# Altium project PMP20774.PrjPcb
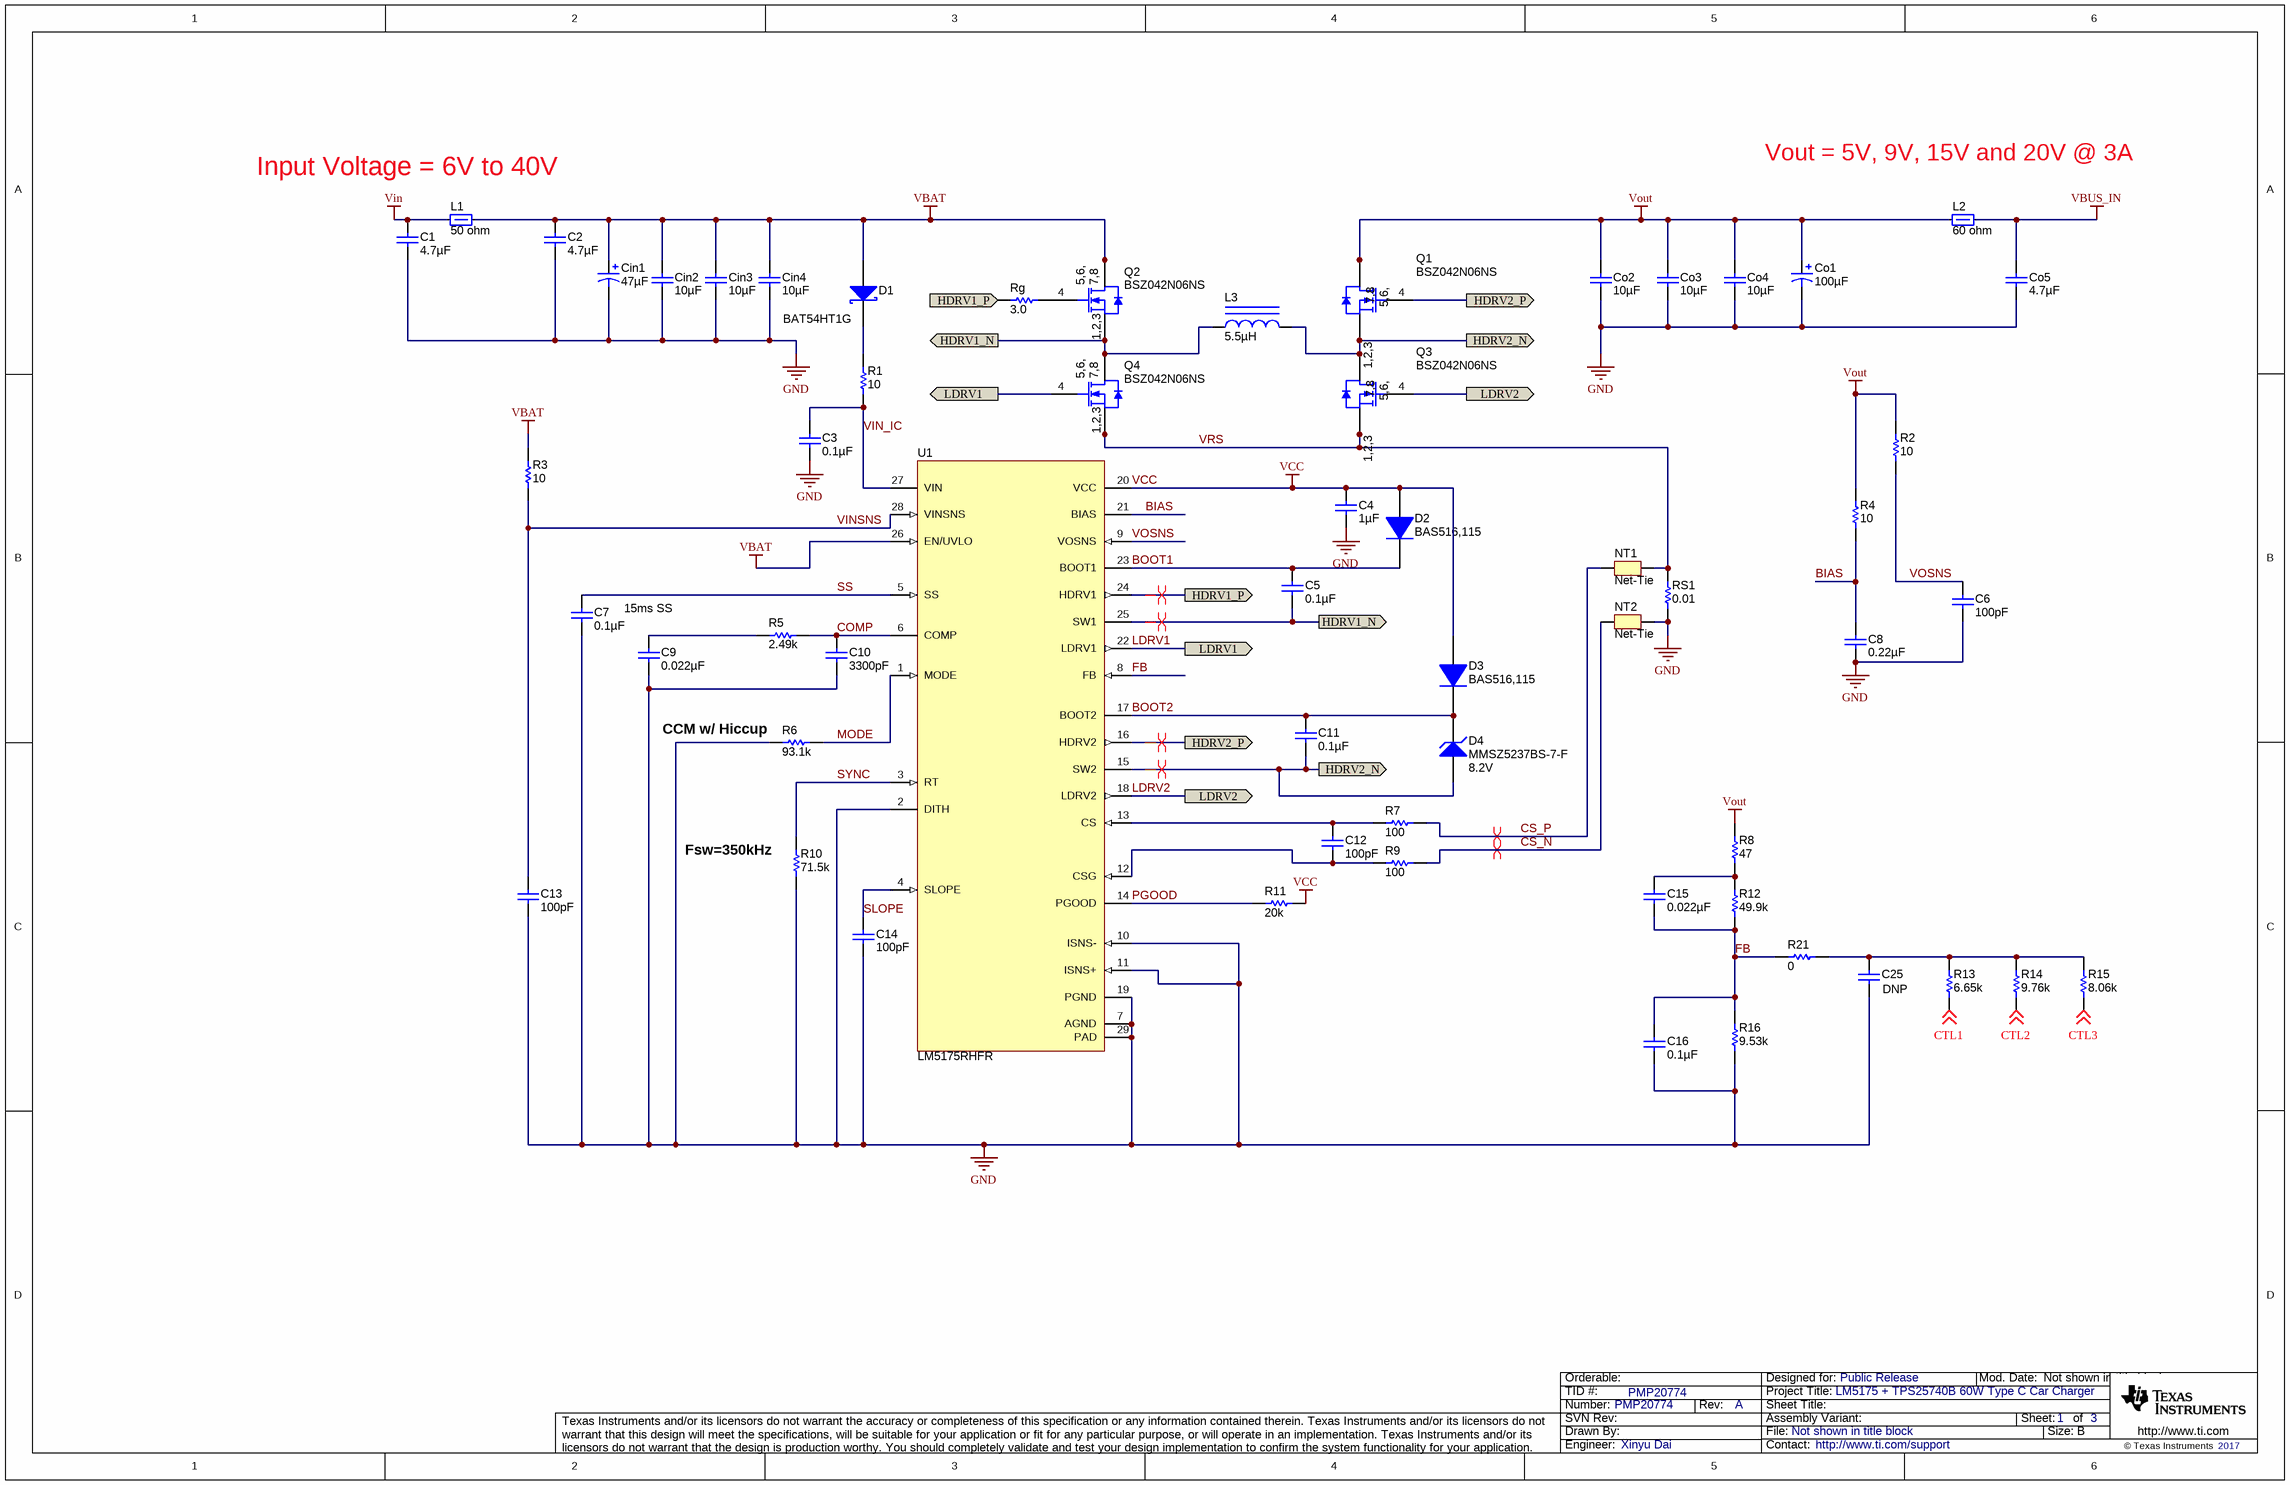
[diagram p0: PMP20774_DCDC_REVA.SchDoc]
CopyrightYear: 2017; PCB_Layout: Xinyu Dai; PCB_Rev: A; PRJ_Customer: Public Release; PRJ_Engineer: Xinyu Dai; PRJ_Number: PMP20774; PRJ_Title: LM5175 + TPS25740B 60W Type C Car Charger; SCH_Rev: A; TechSupport: http://www.ti.com/support; TID: PMP20774
3 sheets, 81 parts. Net scope: flat (ports and power ports of the same name join across sheets).
Board file: PMP20774_REVA.PcbDoc
Sheets:
  PMP20774_DCDC_REVA.SchDoc
  PMP20774_PD_REVA.SchDoc
  PMP20774_REVA_Hardware.SchDoc

## Sheet PMP20774_DCDC_REVA.SchDoc
size 431 x 279 mm; Date: Not shown in title block; ApprovedBy: Not shown in title block; CheckedBy: Not shown in title block; Author: Not shown in title block; CompanyName: Not shown in title block; Engineer: Not shown in title block; Organization: Not shown in title block; Address1: Not shown in title block; Address2: Not shown in title block; Address3: Not shown in title block; Address4: Not shown in title block; DocumentNumber: 1; Revision: Use project parameter SCH_Rev; SheetNumber: 1; SheetTotal: 3; PageSetup: Record=PageOptions¦CenterHorizontal=True¦CenterVertical=True¦PrintScale=1.00¦XCorrection=1.00¦YCorrection=1.00¦PrintKind=0¦BorderSize=5000000¦LeftOffset=0¦BottomOffset=0¦Orientation=2¦PaperLength=1000¦PaperWidth=1000¦Scale=100¦PaperSource=15¦PrintQuality=600¦MediaType=1¦DitherType=10¦PaperKind=Letter¦PrintScaleMode=1

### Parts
(Parts that share a designator on the sheet are numbered #1, #2 ... from top to bottom, then left to right.)
C1  ValueDisplayed: 4.7µF  [1206_180]  (hidden comment: GRM31CR71H475KA12L)
C2  ValueDisplayed: 4.7µF  [1206_180]  (hidden comment: GRM31CR71H475KA12L)
C3  ValueDisplayed: 0.1µF  [0402L]  (hidden comment: GRM155R71H104ME14D)
C4  ValueDisplayed: 1µF  [0402]  (hidden comment: GRM155R70J105KA12D)
C5  ValueDisplayed: 0.1µF  [0402L]  (hidden comment: GRM155R71H104ME14D)
C6  ValueDisplayed: 100pF  [0402L]  (hidden comment: CC0402KRX7R9BB101)
C7  ValueDisplayed: 0.1µF  [0402L]  (hidden comment: GRM155R71H104ME14D)
C8  ValueDisplayed: 0.22µF  [0402L]  (hidden comment: C1005X5R1E224M050BC)
C9  ValueDisplayed: 0.022µF  [0402L]  (hidden comment: GCM155R71H223KA55D)
C10  ValueDisplayed: 3300pF  [0402]  (hidden comment: GRM155R72A332KA01D)
C11  ValueDisplayed: 0.1µF  [0402L]  (hidden comment: GRM155R71H104ME14D)
C12  ValueDisplayed: 100pF  [0402L]  (hidden comment: CC0402KRX7R9BB101)
C13  ValueDisplayed: 100pF  [0402L]  (hidden comment: CC0402KRX7R9BB101)
C14  ValueDisplayed: 100pF  [0402L]  (hidden comment: CC0402KRX7R9BB101)
C15  ValueDisplayed: 0.022µF  [0402L]  (hidden comment: GCM155R71H223KA55D)
C16  ValueDisplayed: 0.1µF  [0402L]  (hidden comment: GRM155R71H104ME14D)
C25  DNP  [0402L]
Cin1  ValueDisplayed: 47µF  [WCAP-ASLI_630x770]  (hidden comment: 865080645012)
Cin2  ValueDisplayed: 10µF  [1210_270]  (hidden comment: GRM32ER71H106MA12)
Cin3  ValueDisplayed: 10µF  [1210_270]  (hidden comment: GRM32ER71H106MA12)
Cin4  ValueDisplayed: 10µF  [1210_270]  (hidden comment: GRM32ER71H106MA12)
Co1  ValueDisplayed: 100µF  [WCAP-ASLI_630x770]  (hidden comment: 865080445010)
Co2  ValueDisplayed: 10µF  [1210_270]  (hidden comment: GRM32ER71H106MA12)
Co3  ValueDisplayed: 10µF  [1210_270]  (hidden comment: GRM32ER71H106MA12)
Co4  ValueDisplayed: 10µF  [1210_270]  (hidden comment: GRM32ER71H106MA12)
Co5  ValueDisplayed: 4.7µF  [1206_180]  (hidden comment: GRM31CR71H475KA12L)
D1  BAT54HT1G  [SOD-323]
D2  BAS516,115  [SOD-523]
D3  BAS516,115  [SOD-523]
D4  MMSZ5237BS-7-F  value 8.2V  [sod-323]
L1  value 50 ohm  [1206L]  (hidden comment: BLM31SN500SN1L)
L2  value 60 ohm  [1206L]  (hidden comment: FBMJ3216HM600-T)
L3  ValueDisplayed: 5.5µH  [WE-HC6]  (hidden comment: 744325550)
NT1  Net-Tie  [Net-Tie_10mil]  (net tie, no BOM)
NT2  Net-Tie  [Net-Tie_10mil]  (net tie, no BOM)
Q1  BSZ042N06NS  [PG-TSDSON-8]
Q2  BSZ042N06NS  [PG-TSDSON-8]
Q3  BSZ042N06NS  [PG-TSDSON-8]
Q4  BSZ042N06NS  [PG-TSDSON-8]
R1  ValueDisplayed: 10  [0402L]  (hidden comment: CRCW040210R0JNED)
R2  ValueDisplayed: 10  [0402L]  (hidden comment: CRCW040210R0JNED)
R3  ValueDisplayed: 10  [0402L]  (hidden comment: CRCW040210R0JNED)
R4  ValueDisplayed: 10  [0402L]  (hidden comment: CRCW040210R0JNED)
R5  ValueDisplayed: 2.49k  [0402L]  (hidden comment: CRCW04022K49FKED)
R6  ValueDisplayed: 93.1k  [0402L]  (hidden comment: CRCW040293K1FKED)
R7  ValueDisplayed: 100  [0402L]  (hidden comment: CRCW0402100RFKED)
R8  ValueDisplayed: 47  [0402L]  (hidden comment: CRCW040247R0JNED)
R9  ValueDisplayed: 100  [0402L]  (hidden comment: CRCW0402100RFKED)
R10  ValueDisplayed: 71.5k  [0402L]  (hidden comment: CRCW040271K5FKED)
R11  ValueDisplayed: 20k  [0402L]  (hidden comment: CRCW040220K0JNED)
R12  ValueDisplayed: 49.9k  [0402L]  (hidden comment: CRCW040249K9FKED)
R13  ValueDisplayed: 6.65k  [0402L]  (hidden comment: CRCW04026K65FKED)
R14  ValueDisplayed: 9.76k  [0402L]  (hidden comment: CRCW04029K76FKED)
R15  ValueDisplayed: 8.06k  [0402L]  (hidden comment: CRCW04028K06FKED)
R16  ValueDisplayed: 9.53k  [0402L]  (hidden comment: CRCW04029K53FKED)
R21#1  ValueDisplayed: 0  [0402L]  (hidden comment: CRCW04020000Z0ED)
Rg  ValueDisplayed: 3.0  [0402L]  (hidden comment: CRCW04023R00JNED)
RS1  ValueDisplayed: 0.01  [0612]  (hidden comment: PRL1632-R010-F-T1)
U1  LM5175RHFR  [RHF0028A]

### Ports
HDRV1_N, HDRV1_P (out), HDRV2_N, HDRV2_P (out), LDRV1 (out), LDRV2 (out)

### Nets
GND: C1.2 C2.2 C3.2 C4.2 C6.2 C7.2 C8.2 C9.2 C10.2 C13.1 C14.2 C16.2 C25.2 Cin1.2(-) Cin2.2 Cin3.2 Cin4.2 Co1.2(-) Co2.2 Co3.2 Co4.2 Co5.2 NT2.1 R6.2 R10.1 R16.1 RS1.1 U1.2(DITH) U1.7(AGND) U1.10(ISNS-) U1.11(ISNS+) U1.19(PGND) U1.29(PAD)
VBAT: C2.1 Cin1.1(+) Cin2.1 Cin3.1 Cin4.1 D1.2(A) L1.2 Q2.5(D) Q2.6(D) Q2.7(D) Q2.8(D) Q2.9(D) R3.1 U1.26(EN/UVLO)
VBUS_IN: Co5.1 L2.2
VCC: C4.1 D2.2(A) D3.2(A) R11.2 U1.20(VCC)
Vin: C1.1 L1.1
Vout: Co1.1(+) Co2.1 Co3.1 Co4.1 L2.1 Q1.5(D) Q1.6(D) Q1.7(D) Q1.8(D) Q1.9(D) R2.2 R4.2 R8.1
BIAS: C8.1 R4.1 U1.21(BIAS)
BOOT1: C5.1 D2.1(K) U1.23(BOOT1)
BOOT2: C11.2 D3.1(K) D4.1(K) U1.17(BOOT2)
COMP: C10.1 R5.2 U1.6(COMP)
CS_N: NT2.2 R9.2
CS_P: NT1.2 R7.2
CTL1: R13.1 ; off-sheet CTL1
CTL2: R14.1 ; off-sheet CTL2
CTL3: R15.1 ; off-sheet CTL3
FB: C15.2 C16.1 R12.1 R16.2 R21#1.1 U1.8(FB)
HDRV1_N: C5.2 L3.1 Q2.1(S) Q2.2(S) Q2.3(S) Q4.5(D) Q4.6(D) Q4.7(D) Q4.8(D) Q4.9(D) U1.25(SW1) ; port HDRV1_N
HDRV1_P: Rg.1 U1.24(HDRV1) ; port HDRV1_P
HDRV2_N: C11.1 D4.2(A) L3.2 Q1.1(S) Q1.2(S) Q1.3(S) Q3.5(D) Q3.6(D) Q3.7(D) Q3.8(D) Q3.9(D) U1.15(SW2) ; port HDRV2_N
HDRV2_P: Q1.4(G) U1.16(HDRV2) ; port HDRV2_P
LDRV1: Q4.4(G) U1.22(LDRV1) ; port LDRV1
LDRV2: Q3.4(G) U1.18(LDRV2) ; port LDRV2
MODE: R6.1 U1.1(MODE)
PGOOD: R11.1 U1.14(PGOOD)
SLOPE: C14.1 U1.4(SLOPE)
SS: C7.1 U1.5(SS)
SYNC: R10.2 U1.3(RT)
VIN_IC: C3.1 R1.1 U1.27(VIN)
VINSNS: C13.2 R3.2 U1.28(VINSNS)
VOSNS: C6.1 R2.1 U1.9(VOSNS)
VRS: NT1.1 Q3.1(S) Q3.2(S) Q3.3(S) Q4.1(S) Q4.2(S) Q4.3(S) RS1.2
NetC9_1: C9.1 R5.1
NetC12_1: C12.1 R7.1 U1.13(CS)
NetC12_2: C12.2 R9.1 U1.12(CSG)
NetC15_1: C15.1 R8.2 R12.2
NetC25_1: C25.1 R13.2 R14.2 R15.2 R21#1.2
NetD1_1: D1.1(K) R1.2
NetQ2_4: Q2.4(G) Rg.2

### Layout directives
differential pair: CS_N, CS_P, HDRV1_N, HDRV1_P, HDRV2_N, HDRV2_P

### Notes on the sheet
- Input Voltage = 6V to 40V
- Vout = 5V, 9V, 15V and 20V @ 3A
- 15ms SS
- (near R6) CCM w/ Hiccup
- (near R10) Fsw=350kHz

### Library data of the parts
C1 C2 = GRM31CR71H475KA12L: CAP, CERM, 4.7 µF, 50 V, +/- 10%, X7R, 1206; Manufacturer: MuRata; Polarized: N; CompType: Capacitor; Value: 4.7uF; U/M: EA; Cap_F: 0.0000047; Tolerance_%: 10; Value1: Unknown; VDC_V: 50; Value2: 50V; TaMin_C: -55; TaMax_C: 125; Cap_Case: 2220; SizeArea_mm2: 5.12; SizeAreaWB_mm2: 10.92; SizeX_mm: 3.2; SizeY_mm: 1.6; SizeZ_mm: 1.8; AEC Category: Q200
C3 C5 C11 = GRM155R71H104ME14D: CAP, CERM, 0.1 µF, 50 V, +/- 20%, X7R, 0402; Manufacturer: MuRata; Polarized: N; CompType: Capacitor; Value: 0.1uF; U/M: EA; Cap_F: 0.0000001; Tolerance_%: 20; Value1: Unknown; VDC_V: 50; Value2: 50V; TaMin_C: -55; TaMax_C: 125; Cap_Case: 0402; AEC Category: Q200; SizeArea_mm2: 0.5; SizeAreaWB_mm2: 3; SizeX_mm: 1; SizeZ_mm: 0.6
C4 = GRM155R70J105KA12D: CAP, CERM, 1 µF, 6.3 V, +/- 10%, X7R, 0402; Manufacturer: MuRata; Polarized: N; CompType: Capacitor; Value: 1uF; U/M: EA; Cap_F: 0.000001; Tolerance_%: 10; Value1: Unknown; VDC_V: 6.3; Value2: 6.3V; TaMin_C: -55; TaMax_C: 125; AEC Category: Q200; SizeArea_mm2: 0.5; SizeAreaWB_mm2: 3; SizeX_mm: 1; SizeZ_mm: 0.6
C6 C13 = CC0402KRX7R9BB101: CAP, CERM, 100 pF, 50 V, +/- 10%, X7R, 0402; Manufacturer: Yageo America; Polarized: N; CompType: Capacitor; Value: 100pF; U/M: EA; Cap_F: 0.0000000001; Tolerance_%: 10; Value1: Unknown; VDC_V: 50; Value2: 50V; TaMin_C: -55; TaMax_C: 125; Cap_Case: 0402; AEC Category: Q200
C7 C16 = GRM155R71H104ME14D: CAP, CERM, 0.1 µF, 50 V, +/- 20%, X7R, 0402; Manufacturer: MuRata; Polarized: N; CompType: Capacitor; Value: 0.1uF; U/M: EA; Cap_F: 0.0000001; Tolerance_%: 20; Value1: Unknown; VDC_V: 50; Value2: 50V; TaMin_C: -55; TaMax_C: 125; Cap_Case: 0402; SizeArea_mm2: 0.5; SizeAreaWB_mm2: 3; SizeX_mm: 1; SizeZ_mm: 0.6; AEC Category: Q200
C8 = C1005X5R1E224M050BC: CAP, CERM, 0.22 µF, 25 V, +/- 20%, X5R, 0402; Manufacturer: TDK; Polarized: N; CompType: Capacitor; Value: 0.22uF; U/M: EA; Cap_F: 0.00000022; Tolerance_%: 20; Value1: Unknown; VDC_V: 25; Value2: 25V; TaMin_C: -55; TaMax_C: 85; Cap_Case: 0402; AEC Category: Q200
C9 C15 = GCM155R71H223KA55D: CAP, CERM, 0.022 µF, 50 V, +/- 10%, C0G/NP0, 0402; Manufacturer: MuRata; Polarized: N; CompType: Capacitor; Value: 0.022uF; U/M: EA; Cap_F: 0.000000022; Tolerance_%: 10; Value1: Unknown; VDC_V: 50; Value2: 50V; TaMin_C: -55; TaMax_C: 125; Cap_Case: 0402; AEC Category: Q200; SizeArea_mm2: 0.5; SizeAreaWB_mm2: 3; SizeX_mm: 1; SizeZ_mm: 0.6
C10 = GRM155R72A332KA01D: CAP, CERM, 3300 pF, 100 V, +/- 10%, X7R, 0402; Manufacturer: MuRata; Polarized: N; CompType: Capacitor; Value: 3300pF; U/M: EA; Cap_F: 0.0000000033; Tolerance_%: 10; Value1: Unknown; VDC_V: 100; Value2: 100V; TaMin_C: -55; TaMax_C: 125; AEC Category: Q200; SizeArea_mm2: 0.5; SizeAreaWB_mm2: 3; SizeX_mm: 1; SizeZ_mm: 0.6
C12 C14 = CC0402KRX7R9BB101: CAP, CERM, 100 pF, 50 V, +/- 10%, X7R, 0402; Manufacturer: Yageo America; Polarized: N; CompType: Capacitor; Value: 100pF; U/M: EA; Cap_F: 0.0000000001; Tolerance_%: 10; Value1: Unknown; VDC_V: 50; Value2: 50V; TaMin_C: -55; TaMax_C: 125; Cap_Case: 0402; AEC Category: Q200; SizeArea_mm2: 0.5; SizeAreaWB_mm2: 3; SizeX_mm: 1; SizeZ_mm: 0.6
C25 = GRM155R70J105MA12D: CAP, CERM, 1 µF, 6.3 V, +/- 20%, X7R, 0402; Manufacturer: MuRata; Polarized: N; CompType: Capacitor; Value: 1uF; ValueDisplayed: 1µF; U/M: EA; Cap_F: 0.000001; Tolerance_%: 20; Value1: Unknown; VDC_V: 6.3; Value2: 6.3V; TaMin_C: -55; TaMax_C: 125; Cap_Case: 0402; SizeArea_mm2: 0.5; SizeAreaWB_mm2: 3; SizeX_mm: 1; SizeZ_mm: 0.6; AEC Category: Q200
Cin1 = 865080645012: CAP, AL, 47 µF, 50 V, +/- 20%, SMD; Manufacturer: Wurth Elektronik; Polarized: Y; CompType: Capacitor; Value: 47uF; U/M: EA; Cap_F: 0.000047; Tolerance_%: 20; Value1: Unknown; VDC_V: 50; Value2: 50V; IRMS_A: 0.23; TaMin_C: -55; TaMax_C: 105; Cap_Case: 6.3x7.7mm; SizeAreaWB_mm2: 79.98; SizeArea_mm2: 48.18; SizeX_mm: 7.3; SizeY_mm: 6.6; SizeZ_mm: 7.7; AEC Category: Q200; AEC Qualified: N
Cin2-Cin4 Co2-Co4 = GRM32ER71H106MA12: CAP, CERM, 10 µF, 50 V, +/- 20%, X7R, 1210; Manufacturer: MuRata; Polarized: N; CompType: Capacitor; Value: 10uF; U/M: EA; Cap_F: 0.00001; Tolerance_%: 20; Value1: Unknown; VDC_V: 50; Value2: 50V; TaMin_C: -55; TaMax_C: 125; Cap_Case: 1210; AEC Category: Q200; SizeArea_mm2: 8; SizeAreaWB_mm2: 14.7; SizeX_mm: 3.2; SizeY_mm: 2.5; SizeZ_mm: 2.7
Co1 = 865080445010: CAP, AL, 100 µF, 25 V, +/- 20%, SMD; Manufacturer: Wurth Elektronik; Polarized: Y; CompType: Capacitor; Value: 100uF; U/M: EA; Cap_F: 0.0001; Tolerance_%: 20; Value1: Unknown; VDC_V: 25; Value2: 25V; IRMS_A: 0.29; TaMin_C: -55; TaMax_C: 105; Cap_Case: 6.3x7.7mm; SizeAreaWB_mm2: 79.98; SizeArea_mm2: 48.18; SizeX_mm: 7.3; SizeY_mm: 6.6; SizeZ_mm: 7.7; AEC Category: Q200; AEC Qualified: N
Co5 = GRM31CR71H475KA12L: CAP, CERM, 4.7 µF, 50 V, +/- 10%, X7R, 1206; Manufacturer: MuRata; Polarized: N; CompType: Capacitor; Value: 4.7uF; U/M: EA; Cap_F: 0.0000047; Tolerance_%: 10; Value1: Unknown; VDC_V: 50; Value2: 50V; TaMin_C: -55; TaMax_C: 125; Cap_Case: 2220; AEC Category: Q200; SizeArea_mm2: 5.12; SizeAreaWB_mm2: 10.92; SizeX_mm: 3.2; SizeY_mm: 1.6; SizeZ_mm: 1.8
D1 = BAT54HT1G: Diode, Schottky, 30 V, 0.2 A, SOD-323; Manufacturer: ON Semiconductor; U/M: EA; Vf_V: 0.35; Value: 30V; Value1: 0.2A; Value2: 0.35V; Io_A: 0.2; Vr_V: 30; SizeAreaWB_mm2: 8.695; SizeArea_mm2: 3.645; SizeX_mm: 2.7; SizeY_mm: 1.35; SizeZ_mm: 1; AEC Category: Q101
D2 D3 = BAS516,115: Diode, Switching, 100V, 0.25A, SOD-523; Manufacturer: NXP Semiconductor; U/M: EA; Vf_V: 1.25; Value2: 1.25V; Io_A: 0.25; Vr_V: 100; TJmax_C: 150
D4 = MMSZ5237BS-7-F: Diode, Zener, 8.2 V, 200 mW, SOD-323; Manufacturer: Diodes Inc.; SymbolCreator: a0412235; U/M: EA; Power_W: 0.2; Vz_V: 8.2; Value1: 0.2W; RJA_CperW: 350; AEC Category: Q101
L1 = BLM31SN500SN1L: Ferrite Bead, 50 ohm @ 100 MHz, 12 A, 1206; Manufacturer: MuRata; Imax_A: 12; DCR_ohm: 0.0016; Value1: 0.0016 ohm; Value2: 12A; ZTyp@100MHz_Ohm: 50
L2 = FBMJ3216HM600-T: Ferrite Bead, 60 ohm @ 100 MHz, 4 A, 1206; Manufacturer: Taiyo Yuden; Imax_A: 4; DCR_ohm: 0.01; Value1: 0.01 ohm; Value2: 4A; ZTyp@100MHz_Ohm: 60
L3 = 744325550: Inductor, Shielded Drum Core, Superflux, 5.5 µH, 10 A, 0.0112 ohm, SMD; Manufacturer: Wurth Elektronik; Value: 5.5uH; Ind_H: 5.5E-6; Imax_A: 10; Irms: 10A @ 50C rise; Isat: 12A @ 30% inductance drop; DCR_ohm: 0.0112; Value2: 10A; AEC Category: Q200; SizeAreaWB_mm2: 158.6; SizeArea_mm2: 112.2; SizeX_mm: 11; SizeY_mm: 10.2; SizeZ_mm: 5
NT1 NT2 = Net-Tie: Single point connection between nets.; SymbolCreator: codlsc
Q1-Q4 = BSZ042N06NS: MOSFET, N-CH, 60 V, 17 A, PG-TSDSON-8; Manufacturer: Infineon Technologies; Alternate Manufacturer: None; U/M: EA; ChType: N; Value: 60V; VdsMax_V: 60; Value1: ? ohm; Value2: 27 nC; QgTyp_nC: 27; Vgs_V: 20; IdsMax_A: 17; AEC Category: Q101; SizeAreaWB_mm2: 19.36; SizeArea_mm2: 11.56; SizeX_mm: 3.4; SizeZ_mm: 1.1
R1 R3 = CRCW040210R0JNED: RES, 10, 5%, 0.063 W, 0402; Manufacturer: Vishay-Dale; CompType: Resistor; Value: 10; Value_Code: 10R0; Tolerance_%: 5; Power_W: 0.063; Value2: 0.063W; VDC_V: 50; TempCo: 200 ppm/C; EIA_Code: E24; U/M: EA; AEC Category: Q200
R2 R4 = CRCW040210R0JNED: RES, 10, 5%, 0.063 W, 0402; Manufacturer: Vishay-Dale; CompType: Resistor; Value_Code: 10R0; Tolerance_%: 5; Power_W: 0.063; Value2: 0.063W; VDC_V: 50; TempCo: 200 ppm/C; EIA_Code: E24; U/M: EA; Value: 10; AEC Category: Q200
R5 = CRCW04022K49FKED: RES, 2.49 k, 1%, 0.063 W, 0402; Manufacturer: Vishay-Dale; CompType: Resistor; Res_ohm: 2490; Value_Code: 2k49; Tolerance_%: 1; Power_W: 0.063; Value2: 0.063W; VDC_V: 50; TempCo: 100 ppm/C; EIA_Code: E96; U/M: EA; Value: 2.49k; AEC Category: Q200; SizeArea_mm2: 0.5; SizeZ_mm: 0.6
R6 = CRCW040293K1FKED: RES, 93.1 k, 1%, 0.063 W, 0402; Manufacturer: Vishay-Dale; CompType: Resistor; Value: 93.1k; Res_ohm: 93100; Value_Code: 93k1; Tolerance_%: 1; Power_W: 0.063; Value2: 0.063W; VDC_V: 50; TempCo: 100 ppm/C; EIA_Code: E96; U/M: EA; AEC Category: Q200; SizeArea_mm2: 0.5; SizeZ_mm: 0.6
R7 R9 = CRCW0402100RFKED: RES, 100, 1%, 0.063 W, 0402; Manufacturer: Vishay-Dale; CompType: Resistor; Value: 100; Value_Code: 100R; Tolerance_%: 1; Power_W: 0.063; Value2: 0.063W; VDC_V: 50; TempCo: 100 ppm/C; EIA_Code: E96; U/M: EA; AEC Category: Q200
R8 = CRCW040247R0JNED: RES, 47, 5%, 0.063 W, 0402; Manufacturer: Vishay-Dale; CompType: Resistor; Value: 47; Value_Code: 47R0; Tolerance_%: 5; Power_W: 0.063; Value2: 0.063W; VDC_V: 50; TempCo: 200 ppm/C; EIA_Code: E24; U/M: EA; AEC Category: Q200
R10 = CRCW040271K5FKED: RES, 71.5 k, 1%, 0.063 W, 0402; Manufacturer: Vishay-Dale; CompType: Resistor; Value: 71.5k; Res_ohm: 71500; Value_Code: 71k5; Tolerance_%: 1; Power_W: 0.063; Value2: 0.063W; VDC_V: 50; TempCo: 100 ppm/C; EIA_Code: E96; U/M: EA; AEC Category: Q200; SizeArea_mm2: 0.5; SizeZ_mm: 0.6
R11 = CRCW040220K0JNED: RES, 20 k, 5%, 0.063 W, 0402; Manufacturer: Vishay-Dale; CompType: Resistor; Value: 20k; Res_ohm: 20000; Value_Code: 20k0; Tolerance_%: 5; Power_W: 0.063; Value2: 0.063W; VDC_V: 50; TempCo: 200 ppm/C; EIA_Code: E24; U/M: EA; AEC Category: Q200
R12 = CRCW040249K9FKED: RES, 49.9 k, 1%, 0.063 W, 0402; Manufacturer: Vishay-Dale; CompType: Resistor; Value: 49.9k; Res_ohm: 49900; Value_Code: 49k9; Tolerance_%: 1; Power_W: 0.063; Value2: 0.063W; VDC_V: 50; TempCo: 100 ppm/C; EIA_Code: E96; U/M: EA; AEC Category: Q200; SizeArea_mm2: 0.5; SizeZ_mm: 0.6
R13 = CRCW04026K65FKED: RES, 6.65 k, 1%, 0.063 W, 0402; Manufacturer: Vishay-Dale; CompType: Resistor; Value: 6.65k; Res_ohm: 6650; Value_Code: 6k65; Tolerance_%: 1; Power_W: 0.063; Value2: 0.063W; VDC_V: 50; TempCo: 100 ppm/C; EIA_Code: E96; U/M: EA; AEC Category: Q200; SizeArea_mm2: 0.5; SizeZ_mm: 0.6
R14 = CRCW04029K76FKED: RES, 9.76 k, 1%, 0.063 W, 0402; Manufacturer: Vishay-Dale; CompType: Resistor; Value: 9.76k; Res_ohm: 9760; Value_Code: 9k76; Tolerance_%: 1; Power_W: 0.063; Value2: 0.063W; VDC_V: 50; TempCo: 100 ppm/C; EIA_Code: E96; U/M: EA; AEC Category: Q200; SizeArea_mm2: 0.5; SizeZ_mm: 0.6
R15 = CRCW04028K06FKED: RES, 8.06 k, 1%, 0.063 W, 0402; Manufacturer: Vishay-Dale; CompType: Resistor; Value: 8.06k; Res_ohm: 8060; Value_Code: 8k06; Tolerance_%: 1; Power_W: 0.063; Value2: 0.063W; VDC_V: 50; TempCo: 100 ppm/C; EIA_Code: E96; U/M: EA; AEC Category: Q200; SizeArea_mm2: 0.5; SizeZ_mm: 0.6
R16 = CRCW04029K53FKED: RES, 9.53 k, 1%, 0.063 W, 0402; Manufacturer: Vishay-Dale; CompType: Resistor; Value: 9.53k; Res_ohm: 9530; Value_Code: 9k53; Tolerance_%: 1; Power_W: 0.063; Value2: 0.063W; VDC_V: 50; TempCo: 100 ppm/C; EIA_Code: E96; U/M: EA; AEC Category: Q200; SizeArea_mm2: 0.5; SizeZ_mm: 0.6
R21#1 = CRCW04020000Z0ED: RES, 0, 5%, 0.063 W, 0402; Manufacturer: Vishay-Dale; CompType: Resistor; Value: 0; Value_Code: 0000; Tolerance_%: 5; Power_W: 0.063; Value2: 0.063W; VDC_V: 50; TempCo: 200 ppm/C; SizeArea_mm2: 0.5; SizeX_mm: 1; SizeZ_mm: 0.6; EIA_Code: E24; U/M: EA; AEC Category: Q200
Rg = CRCW04023R00JNED: RES, 3.0, 5%, 0.063 W, 0402; Manufacturer: Vishay-Dale; CompType: Resistor; Value: 3.0; Res_ohm: 3; Value_Code: 3R00; Tolerance_%: 5; Power_W: 0.063; Value2: 0.063W; VDC_V: 50; TempCo: 200 ppm/C; SizeArea_mm2: 0.5; SizeX_mm: 1; SizeZ_mm: 0.6; EIA_Code: E24; U/M: EA; AEC Category: Q200
RS1 = PRL1632-R010-F-T1: RES, 0.01, 1%, 1 W, 0612; Manufacturer: Susumu Co Ltd; CompType: Resistor; Value: 0.01; Tolerance_%: 1; TempCo: 200 ppm/C; U/M: EA; Value_Code: R010; Value2: 1W; EIA_Code: E96; AEC Category: Q200; SizeArea_mm2: 5.12; SizeAreaWB_mm2: 10.92; SizeX_mm: 1.6; SizeY_mm: 3.2; SizeZ_mm: 0.85
U1 = LM5175RHFR: 42-V Wide VIN Synchronous 4-Switch Buck-Boost Controller, RHF0028A; Alternate PartNumber: LM5175RHFT; Manufacturer: Texas Instruments; SymbolCreator: Altium; CompType: IC; U/M: EA

## Sheet PMP20774_PD_REVA.SchDoc
size 431 x 279 mm; Date: Not shown in title block; ApprovedBy: Not shown in title block; CheckedBy: Not shown in title block; Author: Not shown in title block; CompanyName: Not shown in title block; Engineer: Not shown in title block; Organization: Not shown in title block; Address1: Not shown in title block; Address2: Not shown in title block; Address3: Not shown in title block; Address4: Not shown in title block; DocumentNumber: 2; Revision: Use project parameter SCH_Rev; SheetNumber: 2; SheetTotal: 3; PageSetup: Record=PageOptions¦CenterHorizontal=True¦CenterVertical=True¦PrintScale=1.00¦XCorrection=1.00¦YCorrection=1.00¦PrintKind=0¦BorderSize=5000000¦LeftOffset=0¦BottomOffset=0¦Orientation=2¦PaperLength=1000¦PaperWidth=1000¦Scale=100¦PaperSource=15¦PrintQuality=600¦MediaType=1¦DitherType=10¦PaperKind=Letter¦PrintScaleMode=1
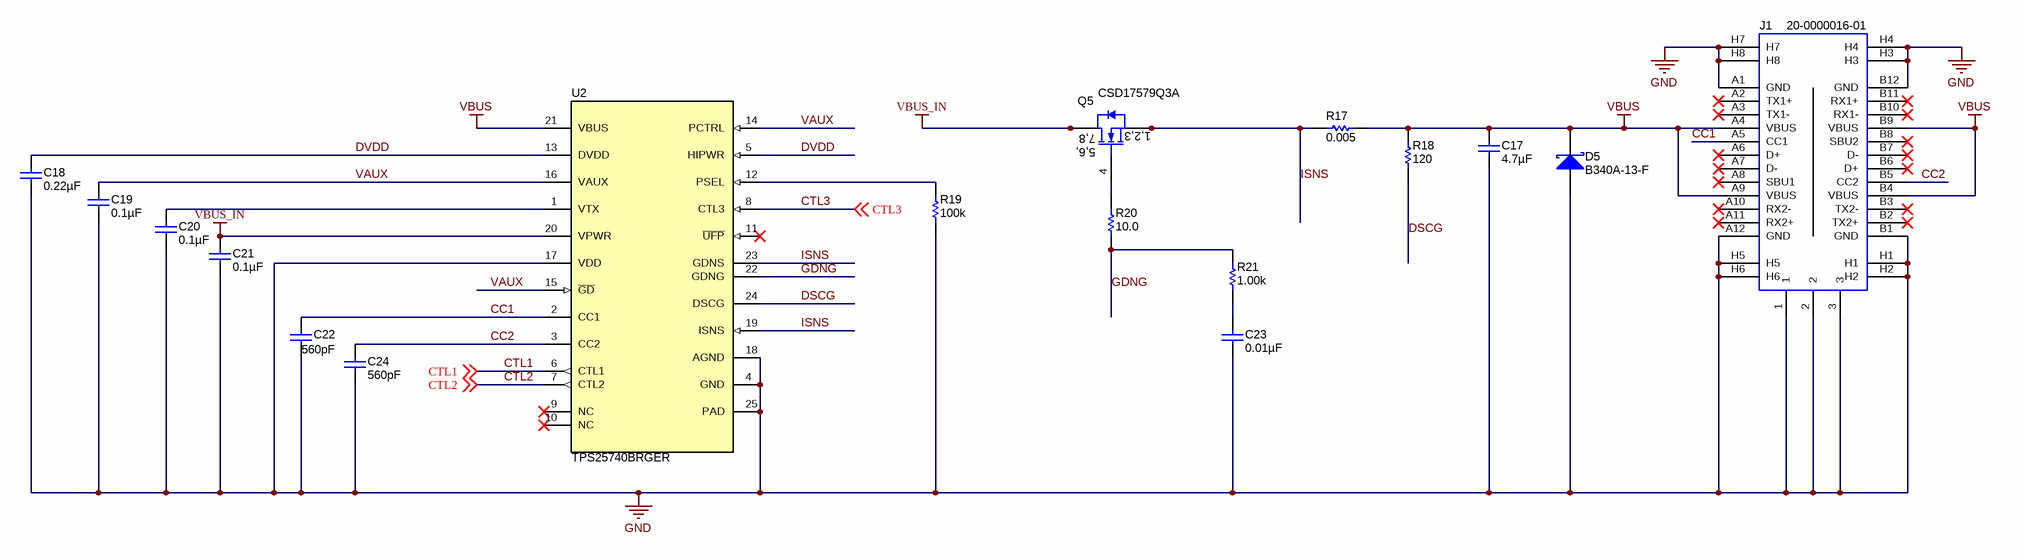
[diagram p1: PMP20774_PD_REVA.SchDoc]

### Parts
(Parts that share a designator on the sheet are numbered #1, #2 ... from top to bottom, then left to right.)
C17  ValueDisplayed: 4.7µF  [0805L]  (hidden comment: GRM21BR71E475KA73L)
C18  ValueDisplayed: 0.22µF  [0402L]  (hidden comment: GRM155R71A224KE01D)
C19  ValueDisplayed: 0.1µF  [0402L]  (hidden comment: GRM155R71H104ME14D)
C20  ValueDisplayed: 0.1µF  [0402L]  (hidden comment: GRM155R71H104ME14D)
C21  ValueDisplayed: 0.1µF  [0402L]  (hidden comment: GRM155R71H104ME14D)
C22  ValueDisplayed: 560pF  [0402L]  (hidden comment: GRM1555C1H561JA01D)
C23  ValueDisplayed: 0.01µF  [0402L]  (hidden comment: GCM155R71E103KA37D)
C24  ValueDisplayed: 560pF  [0402L]  (hidden comment: GRM1555C1H561JA01D)
D5  B340A-13-F  [SMA]
J1  20-0000016-01  [Lintes_20-0000016-01]
Q5  CSD17579Q3A  [DNH0008A_NV]
R17  ValueDisplayed: 0.005  [1206L]  (hidden comment: WSL12065L000FEA)
R18  ValueDisplayed: 120  [1206L]  (hidden comment: ERJ-P08J121V)
R19  ValueDisplayed: 100k  [0402L]  (hidden comment: CRCW0402100KJNED)
R20  ValueDisplayed: 10.0  [0402L]  (hidden comment: CRCW040210R0FKED)
R21#2  ValueDisplayed: 1.00k  [0402L]  (hidden comment: CRCW04021K00FKED)
U2  TPS25740BRGER  [RGE0024F]

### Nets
GND: C17.2 C18.1 C19.2 C20.2 C21.2 C22.2 C23.2 C24.2 D5.2(A) J1.1 J1.2 J1.3 J1.A1(GND) J1.A12(GND) J1.B1(GND) J1.B12(GND) J1.H1 J1.H2 J1.H3 J1.H4 J1.H5 J1.H6 J1.H7 J1.H8 R19.2 U2.4(GND) U2.17(VDD) U2.18(AGND) U2.25(PAD)
VBUS: C17.1 D5.1(K) J1.A4(VBUS) J1.A9(VBUS) J1.B4(VBUS) J1.B9(VBUS) R17.2 R18.2 U2.21(VBUS)
VBUS_IN: C21.1 Q5.5(D) Q5.6(D) Q5.7(D) Q5.8(D) Q5.9(D) U2.20(VPWR)
CC1: C22.1 J1.A5(CC1) U2.2(CC1)
CC2: C24.1 J1.B5(CC2) U2.3(CC2)
CTL1: U2.6(CTL1) ; off-sheet CTL1
CTL2: U2.7(CTL2) ; off-sheet CTL2
CTL3: U2.8(CTL3) ; off-sheet CTL3
DSCG: R18.1 U2.24(DSCG)
DVDD: C18.2 U2.5(HIPWR) U2.13(DVDD)
GDNG: R20.1 R21#2.2 U2.22(GDNG)
ISNS: Q5.1(S) Q5.2(S) Q5.3(S) R17.1 U2.19(ISNS) U2.23(GDNS)
VAUX: C19.1 U2.14(PCTRL) U2.15(~{GD}) U2.16(VAUX)
NetC20_1: C20.1 U2.1(VTX)
NetC23_1: C23.1 R21#2.1
NetQ5_4: Q5.4(G) R20.2
NetR19_1: R19.1 U2.12(PSEL)

Not connected (* = marked no-connect by the designer): J1 A2(TX1+)* A3(TX1-)* A6(D+)* A7(D-)* A8(SBU1)* A10(RX2-)* A11(RX2+)* B2(TX2+)* B3(TX2-)* B6(D+)* B7(D-)* B8(SBU2)* B10(RX1-)* B11(RX1+)*; U2 9(NC)* 10(NC)* 11(~{UFP})*

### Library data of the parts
C17 = GRM21BR71E475KA73L: CAP, CERM, 4.7 µF, 25 V, +/- 10%, X7R, 0805; Manufacturer: MuRata; Polarized: N; CompType: Capacitor; Value: 4.7uF; U/M: EA; Cap_F: 0.0000047; Tolerance_%: 10; Value1: Unknown; VDC_V: 25; Value2: 25V; TaMin_C: -55; TaMax_C: 125; Cap_Case: 0805; SizeArea_mm2: 2.5; SizeAreaWB_mm2: 6.75; SizeX_mm: 2; SizeY_mm: 1.25; SizeZ_mm: 1.45; AEC Category: Q200
C18 = GRM155R71A224KE01D: CAP, CERM, 0.22 µF, 10 V, +/- 10%, X7R, 0402; Manufacturer: MuRata; Polarized: N; CompType: Capacitor; Value: 0.22uF; U/M: EA; Cap_F: 0.00000022; Tolerance_%: 10; Value1: Unknown; Value2: 10V; TaMin_C: -55; TaMax_C: 125; Cap_Case: 0402; SizeArea_mm2: 0.5; SizeAreaWB_mm2: 3; SizeX_mm: 1; SizeZ_mm: 0.6; AEC Category: Q200
C19-C21 = GRM155R71H104ME14D: as C7 on sheet PMP20774_DCDC_REVA
C22 C24 = GRM1555C1H561JA01D: CAP, CERM, 560 pF, 50 V, +/- 5%, C0G/NP0, 0402; Manufacturer: MuRata; Polarized: N; CompType: Capacitor; Value: 560pF; U/M: EA; Cap_F: 0.00000000056; Tolerance_%: 5; Value1: Unknown; VDC_V: 50; Value2: 50V; TaMin_C: -55; TaMax_C: 125; Cap_Case: 0402; SizeArea_mm2: 0.5; SizeAreaWB_mm2: 3; SizeX_mm: 1; SizeZ_mm: 0.6; AEC Category: Q200
C23 = GCM155R71E103KA37D: CAP, CERM, 0.01 µF, 25 V, +/- 10%, X7R, 0402; Manufacturer: MuRata; Polarized: N; CompType: Capacitor; Value: 0.01uF; U/M: EA; Cap_F: 0.00000001; Tolerance_%: 10; Value1: Unknown; VDC_V: 25; Value2: 25V; TaMin_C: -55; TaMax_C: 125; Cap_Case: 0402; SizeArea_mm2: 0.5; SizeAreaWB_mm2: 3; SizeX_mm: 1; SizeZ_mm: 0.6; AEC Category: Q200
D5 = B340A-13-F: Diode, Schottky, 40 V, 3 A, SMA; Manufacturer: Diodes Inc.; U/M: EA; Vf_V: 0.5; Value: 40V; Value1: 3A; Value2: 0.5V; Io_A: 3; Vr_V: 40; TJmax_C: 125; RJC_CperW: 25; SizeAreaWB_mm2: 37.3428; SizeArea_mm2: 16.3228; SizeX_mm: 5.59; SizeY_mm: 2.92; SizeZ_mm: 2.87; AEC Category: Q101
J1 = 20-0000016-01: Connector, Receptacle, USB Type C, R/A, SMT; Manufacturer: Lintes Technology; SymbolCreator: Altium; U/M: EA
Q5 = CSD17579Q3A: MOSFET, N-CH, 30 V, 20 A, DNH0008A (VSONP-8); Manufacturer: Texas Instruments; Alternate Manufacturer: None; U/M: EA; ChType: N; Value: 30V; VdsMax_V: 30; Value1: 0.0142 ohm; Rdson45_ohm: 0.0142; Value2: 5.3 nC; QgTyp_nC: 5.3; Vgs_V: 20; SizeAreaWB_mm2: 18.49; SizeArea_mm2: 10.89; SizeX_mm: 3.3; SizeZ_mm: 0.9; AEC Category: Q101
R17 = WSL12065L000FEA: RES, 0.005, 1%, 0.25 W, 1206; Manufacturer: Vishay-Dale; CompType: Resistor; Value: 0.005; Value_Code: 5L000; Tolerance_%: 1; Power_W: 0.25; Value2: 0.25W; TempCo: 110 ppm/C; SizeArea_mm2: 5.12; SizeX_mm: 3.2; SizeY_mm: 1.6; SizeZ_mm: 1.35; EIA_Code: E96; U/M: EA; AEC Category: Q200; AEC Qualified: N
R18 = ERJ-P08J121V: RES, 120, 5%, 0.667 W, AEC-Q200 Grade 0, 1206; Manufacturer: Panasonic; CompType: Resistor; Value: 120; Value_Code: 120R; Tolerance_%: 5; Power_W: 0.667; Value2: 0.667W; VDC_V: 500; TempCo: 200 ppm/C; SizeArea_mm2: 5.12; SizeX_mm: 3.2; SizeY_mm: 1.6; SizeZ_mm: 1.35; EIA_Code: E24; U/M: EA; AEC Category: Q200; AEC Qualified: Y; AEC Grade: 0
R19 = CRCW0402100KJNED: RES, 100 k, 5%, 0.063 W, 0402; Manufacturer: Vishay-Dale; CompType: Resistor; Value: 100k; Res_ohm: 100000; Tolerance_%: 5; Power_W: 0.063; Value2: 0.063W; VDC_V: 50; TempCo: 200 ppm/C; SizeArea_mm2: 0.5; SizeX_mm: 1; SizeZ_mm: 0.6; EIA_Code: E24; U/M: EA; AEC Category: Q200
R20 = CRCW040210R0FKED: RES, 10.0, 1%, 0.063 W, 0402; Manufacturer: Vishay-Dale; CompType: Resistor; Value: 10.0; Res_ohm: 10; Value_Code: 10R0; Tolerance_%: 1; Power_W: 0.063; Value2: 0.063W; VDC_V: 50; TempCo: 100 ppm/C; SizeArea_mm2: 0.5; SizeZ_mm: 0.6; EIA_Code: E96; U/M: EA; AEC Category: Q200
R21#2 = CRCW04021K00FKED: RES, 1.00 k, 1%, 0.063 W, 0402; Manufacturer: Vishay-Dale; CompType: Resistor; Value: 1.00k; Res_ohm: 1000; Value_Code: 1k00; Tolerance_%: 1; Power_W: 0.063; Value2: 0.063W; VDC_V: 50; TempCo: 100 ppm/C; SizeArea_mm2: 0.5; SizeZ_mm: 0.6; EIA_Code: E96; U/M: EA; AEC Category: Q200
U2 = TPS25740BRGER: USB Type-C and USB PD Source Controller, RGE0024F (VQFN-24); Alternate PartNumber: TPS25740BRGET; Manufacturer: Texas Instruments; SymbolCreator: a0411947; SizeArea_mm2: 16; SizeAreaWB_mm2: 25; SizeX_mm: 4; SizeZ_mm: 1; CompType: IC; U/M: EA

## Sheet PMP20774_REVA_Hardware.SchDoc
size 431 x 279 mm; Date: Not shown in title block; ApprovedBy: Not shown in title block; CheckedBy: Not shown in title block; Author: Not shown in title block; CompanyName: Not shown in title block; Engineer: Not shown in title block; Organization: Not shown in title block; Address1: Not shown in title block; Address2: Not shown in title block; Address3: Not shown in title block; Address4: Not shown in title block; DocumentNumber: 3; Revision: Use project parameter SCH_Rev; SheetNumber: 3; SheetTotal: 3; PageSetup: Record=PageOptions¦CenterHorizontal=True¦CenterVertical=True¦PrintScale=1.00¦XCorrection=1.00¦YCorrection=1.00¦PrintKind=0¦BorderSize=5000000¦LeftOffset=0¦BottomOffset=0¦Orientation=2¦PaperLength=1000¦PaperWidth=1000¦Scale=100¦PaperSource=15¦PrintQuality=600¦MediaType=1¦DitherType=10¦PaperKind=Letter¦PrintScaleMode=1
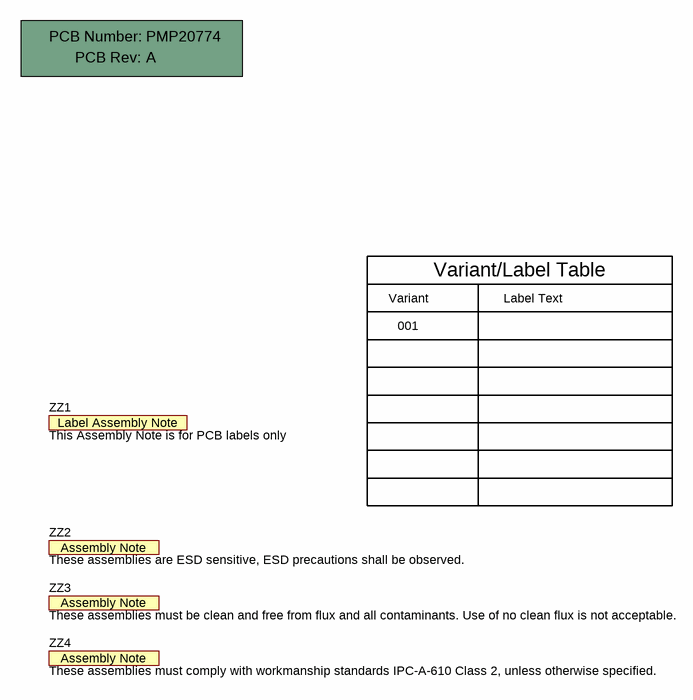
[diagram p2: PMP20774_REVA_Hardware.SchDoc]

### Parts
!PCB  Printed Circuit Board  (value not drawn)  (mechanical)
ZZ1  This Assembly Note is for PCB labels only  [AssemblyNoteLabel]  (no BOM)
ZZ2  These assemblies are ESD sensitive, ESD precautions shall be observed.  [AssemblyNote]  (no BOM)
ZZ3  These assemblies must be clean and free from flux and all contaminants. Use of no clean flux is not acceptable.  [AssemblyNote]  (no BOM)
ZZ4  These assemblies must comply with workmanship standards IPC-A-610 Class 2, unless otherwise specified.  [AssemblyNote]  (no BOM)

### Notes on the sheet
- Variant
- Variant/Label Table
- Label Text
- 001

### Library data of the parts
!PCB = PCB: Manufacturer: Any; PartNumber: PMP20774; SymbolCreator: a0412235
ZZ1 = AssemblyNoteLabel: SymbolCreator: a0412235
ZZ2-ZZ4 = AssemblyNote: SymbolCreator: codlsc

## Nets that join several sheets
GND: PMP20774_DCDC_REVA (33 pins), PMP20774_PD_REVA (29 pins)
VBUS_IN: PMP20774_DCDC_REVA (Co5.1 L2.2), PMP20774_PD_REVA (7 pins)
CTL1: PMP20774_DCDC_REVA (R13.1), PMP20774_PD_REVA (U2.6)
CTL2: PMP20774_DCDC_REVA (R14.1), PMP20774_PD_REVA (U2.7)
CTL3: PMP20774_DCDC_REVA (R15.1), PMP20774_PD_REVA (U2.8)

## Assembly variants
001: not fitted C25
